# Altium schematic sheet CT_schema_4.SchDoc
size 517 x 390 mm
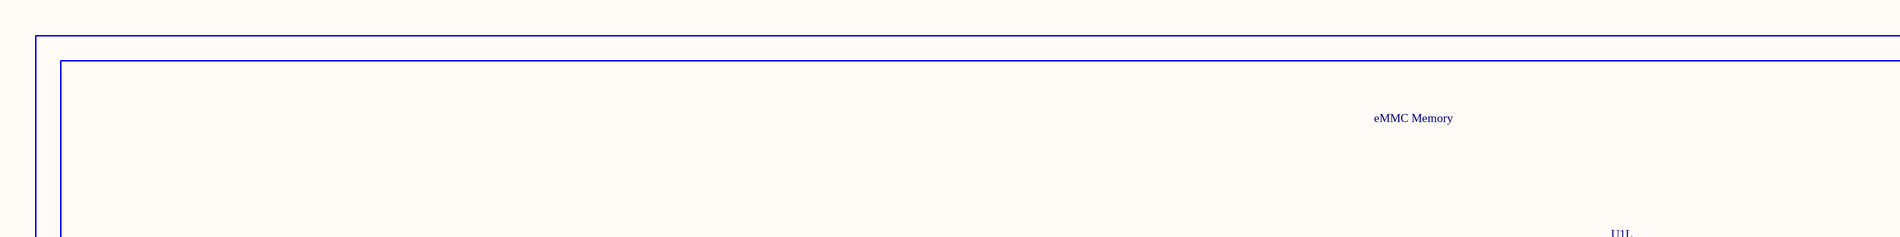
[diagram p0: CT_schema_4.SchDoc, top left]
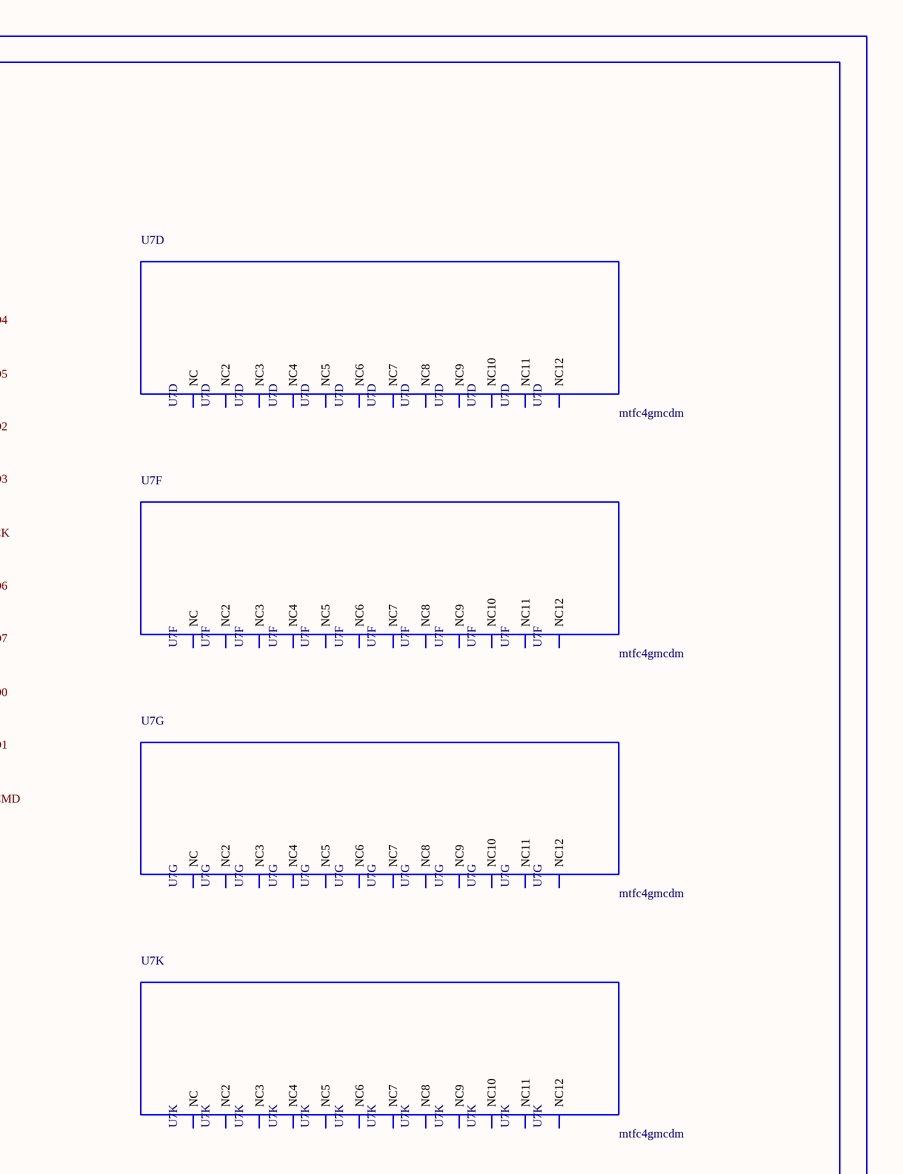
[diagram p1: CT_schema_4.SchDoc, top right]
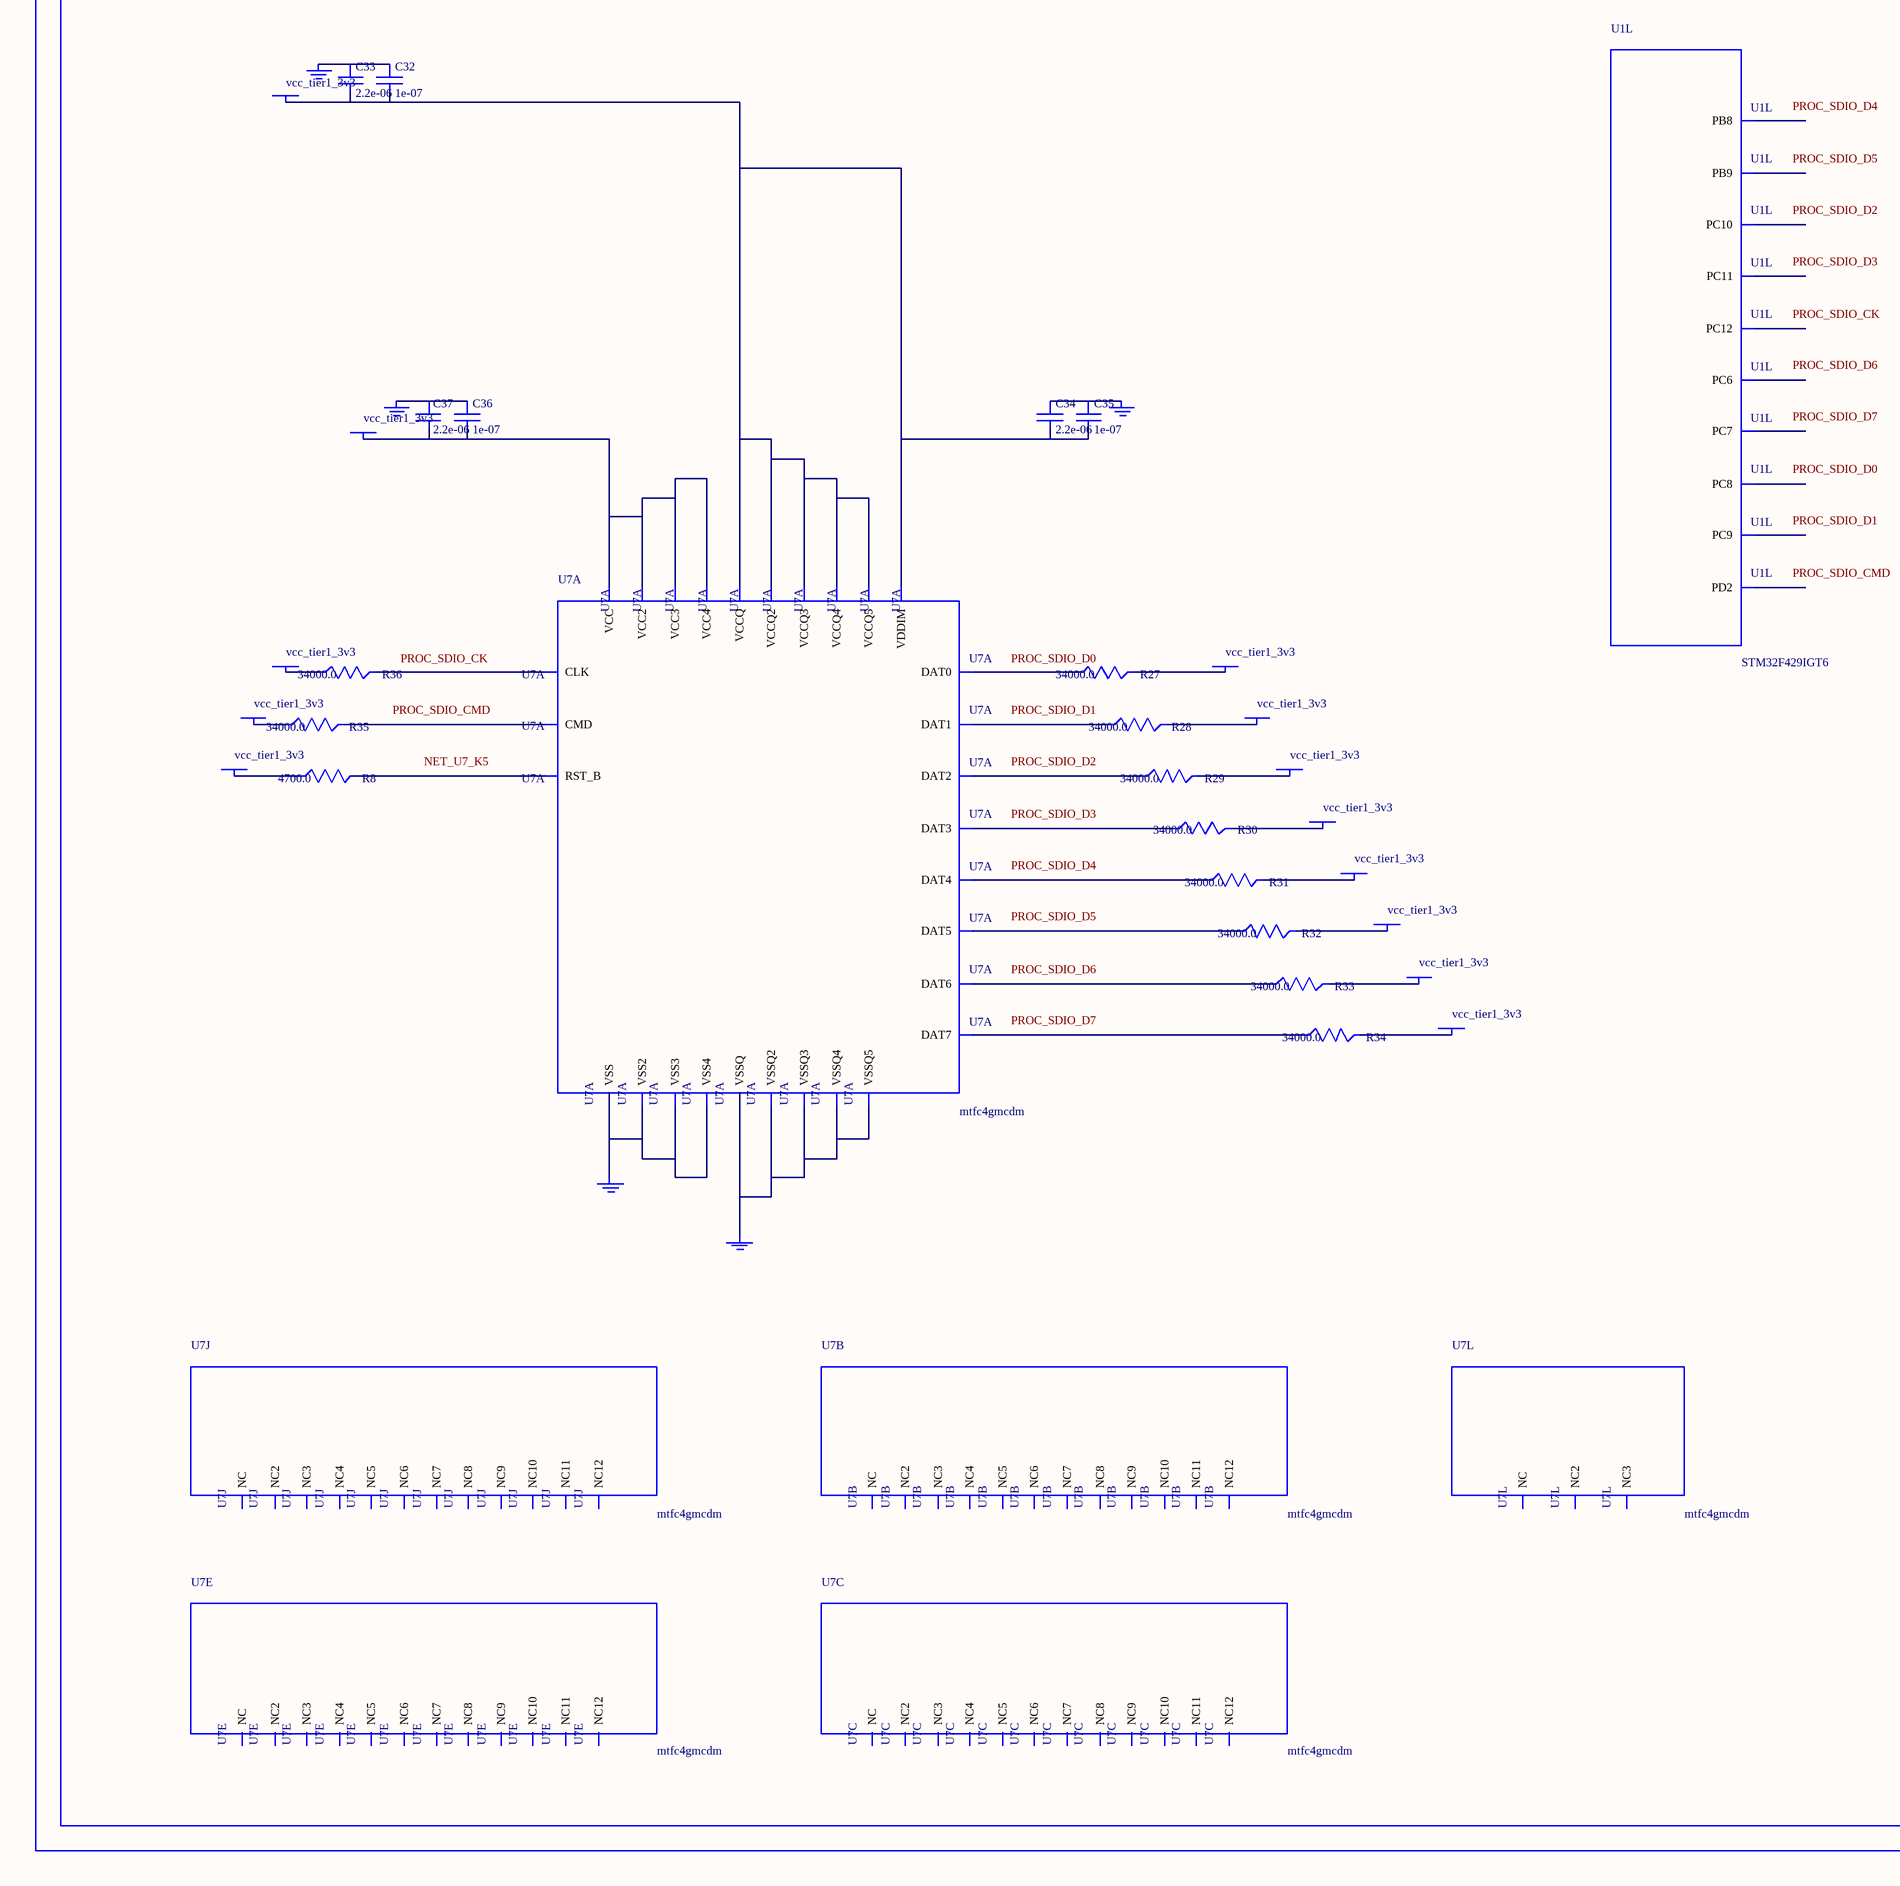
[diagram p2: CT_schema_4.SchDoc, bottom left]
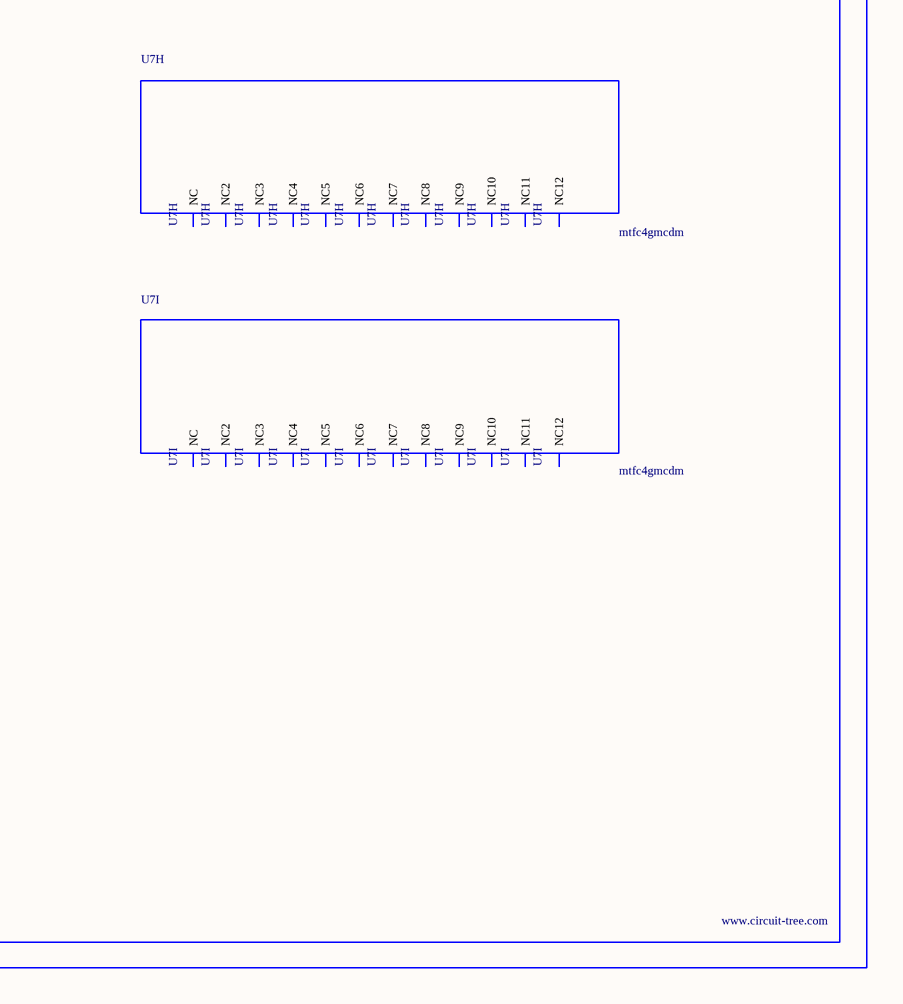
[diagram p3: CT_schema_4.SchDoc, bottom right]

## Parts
BORDER3  (no value)
C32  1e-07  [C0402]
C33  2.2e-06  [C0603]
C34  2.2e-06  [C0603]
C35  1e-07  [C0402]
C36  1e-07  [C0402]
C37  2.2e-06  [C0603]
GND_INSTANCE_3_0  (no value)
GND_INSTANCE_3_1  (no value)
GND_INSTANCE_3_2  (no value)
GND_INSTANCE_3_3  (no value)
GND_INSTANCE_3_4  (no value)
POWER_INSTANCE_3_0  vcc_tier1_3v3
POWER_INSTANCE_3_1  vcc_tier1_3v3
POWER_INSTANCE_3_2  vcc_tier1_3v3
POWER_INSTANCE_3_3  vcc_tier1_3v3
POWER_INSTANCE_3_4  vcc_tier1_3v3
POWER_INSTANCE_3_5  vcc_tier1_3v3
POWER_INSTANCE_3_6  vcc_tier1_3v3
POWER_INSTANCE_3_7  vcc_tier1_3v3
POWER_INSTANCE_3_8  vcc_tier1_3v3
POWER_INSTANCE_3_9  vcc_tier1_3v3
POWER_INSTANCE_3_10  vcc_tier1_3v3
POWER_INSTANCE_3_11  vcc_tier1_3v3
POWER_INSTANCE_3_12  vcc_tier1_3v3
R8  4700.0  [R0603]
R27  34000.0  [R0603]
R28  34000.0  [R0603]
R29  34000.0  [R0603]
R30  34000.0  [R0603]
R31  34000.0  [R0603]
R32  34000.0  [R0603]
R33  34000.0  [R0603]
R34  34000.0  [R0603]
R35  34000.0  [R0603]
R36  34000.0  [R0603]
U1  STM32F429IGT6  [LQFP176]  (part L of 15)
U7  mtfc4gmcdm  [TFBGA-153]  (parts A,B,C,D,E,F,G,H,I,J,K,L of 12)

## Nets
NetC32_1: C32.1 C33.1 GND_INSTANCE_3_0.0(GND)
NetC32_2: C32.2 C33.2 C34.2 C35.2 POWER_INSTANCE_3_0.0(PWR) U7.C2(VDDIM) U7.C6(VCCQ) U7.M4(VCCQ2) U7.N4(VCCQ3) U7.P3(VCCQ4) U7.P5(VCCQ5)
NetC34_1: C34.1 C35.1 GND_INSTANCE_3_1.0(GND)
NetC36_1: C36.1 C37.1 GND_INSTANCE_3_2.0(GND)
NetC36_2: C36.2 C37.2 POWER_INSTANCE_3_1.0(PWR) U7.E6(VCC) U7.F5(VCC2) U7.J10(VCC3) U7.K9(VCC4)
NetGND_INSTANCE_3_3_0: GND_INSTANCE_3_3.0(GND) U7.E7(VSS) U7.G5(VSS2) U7.H10(VSS3) U7.K8(VSS4)
NetGND_INSTANCE_3_4_0: GND_INSTANCE_3_4.0(GND) U7.C4(VSSQ) U7.N2(VSSQ2) U7.N5(VSSQ3) U7.P4(VSSQ4) U7.P6(VSSQ5)
NetPOWER_INSTANCE_3_2_0: POWER_INSTANCE_3_2.0(PWR) R27.2
NetPOWER_INSTANCE_3_3_0: POWER_INSTANCE_3_3.0(PWR) R28.2
NetPOWER_INSTANCE_3_4_0: POWER_INSTANCE_3_4.0(PWR) R29.2
NetPOWER_INSTANCE_3_5_0: POWER_INSTANCE_3_5.0(PWR) R30.2
NetPOWER_INSTANCE_3_6_0: POWER_INSTANCE_3_6.0(PWR) R31.2
NetPOWER_INSTANCE_3_7_0: POWER_INSTANCE_3_7.0(PWR) R32.2
NetPOWER_INSTANCE_3_8_0: POWER_INSTANCE_3_8.0(PWR) R33.2
NetPOWER_INSTANCE_3_9_0: POWER_INSTANCE_3_9.0(PWR) R34.2
NetPOWER_INSTANCE_3_10_0: POWER_INSTANCE_3_10.0(PWR) R35.1
NetPOWER_INSTANCE_3_11_0: POWER_INSTANCE_3_11.0(PWR) R36.1
NetPOWER_INSTANCE_3_12_0: POWER_INSTANCE_3_12.0(PWR) R8.1
NetR8_2: R8.2 U7.K5(RST_B)
NetR27_1: R27.1 U7.A3(DAT0)
NetR28_1: R28.1 U7.A4(DAT1)
NetR29_1: R29.1 U7.A5(DAT2)
NetR30_1: R30.1 U7.B2(DAT3)
NetR31_1: R31.1 U7.B3(DAT4)
NetR32_1: R32.1 U7.B4(DAT5)
NetR33_1: R33.1 U7.B5(DAT6)
NetR34_1: R34.1 U7.B6(DAT7)
NetR35_2: R35.2 U7.M5(CMD)
NetR36_2: R36.2 U7.M6(CLK)

Not connected (* = marked no-connect by the designer): U1 115(PC6) 116(PC7) 117(PC8) 118(PC9) 139(PC10) 140(PC11) 141(PC12) 144(PD2) 167(PB8) 168(PB9); U7 A1(NC) A2(NC7) A6(NC8) A7(NC9) A8(NC10) A9(NC11) A10(NC2) A11(NC3) A12(NC4) A13(NC5) A14(NC6) B1(NC12) B7(NC6) B8(NC7) B9(NC8) B10(NC) B11(NC2) B12(NC3) B13(NC4) B14(NC5) C1(NC9) C3(NC10) C5(NC11) C7(NC12) C8(NC6) C9(NC7) C10(NC) C11(NC2) C12(NC3) C13(NC4) C14(NC5) D1(NC8) D2(NC10) D3(NC11) D4(NC12) D12(NC9) D13(NC) D14(NC2) E1(NC3) E2(NC8) E3(NC9) E5(NC10) E8(NC11) E9(NC12) E10(NC4) E12(NC5) E13(NC6) E14(NC7) F1(NC) F2(NC6) F3(NC7) F10(NC2) F12(NC3) F13(NC4) F14(NC5) G1(NC8) G2(NC11) G3(NC12) G10(NC9) G12(NC10) G13(NC) G14(NC2) H1(NC3) H2(NC7) H3(NC8) H5(NC9) H12(NC4) H13(NC5) H14(NC6) J1(NC10) J2(NC11) J3(NC12) J5(NC4) J12(NC) J13(NC2) J14(NC3) K1(NC5) K2(NC9) K3(NC10) K6(NC11) K7(NC12) K10(NC6) K12(NC7) K13(NC8) K14(NC) L1(NC2) L2(NC6) L3(NC7) L12(NC3) L13(NC4) L14(NC5) M1(NC8) M2(NC9) M3(NC10) M7(NC11) M8(NC12) M9(NC6) M10(NC) M11(NC2) M12(NC3) M13(NC4) M14(NC5) N1(NC7) N3(NC8) N6(NC9) N7(NC10) N8(NC11) N9(NC12) N10(NC) N11(NC2) N12(NC3) N13(NC4) N14(NC5) P1(NC6) P2(NC9) P7(NC10) P8(NC11) P9(NC12) P10(NC7) P11(NC8) P12(NC) P13(NC2) P14(NC3)

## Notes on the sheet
- Labels drawn without touching a wire or pin: NET_U7_K5, PROC_SDIO_CK, PROC_SDIO_CMD, PROC_SDIO_D0, PROC_SDIO_D1, PROC_SDIO_D2, PROC_SDIO_D3, PROC_SDIO_D4, PROC_SDIO_D5, PROC_SDIO_D6, PROC_SDIO_D7

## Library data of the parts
BORDER3 = BORDER_PAGE3
C32 C35 C36 = C0402C104K3RACTU
C33 C34 C37 = C0603C225K8RACTU
GND_INSTANCE_3_0-GND_INSTANCE_3_4 = GND
POWER_INSTANCE_3_0-POWER_INSTANCE_3_12 = PWR
R8 = RC0603JR-074K7L
R27-R36 = ERA3ARB3402V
